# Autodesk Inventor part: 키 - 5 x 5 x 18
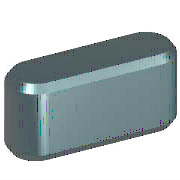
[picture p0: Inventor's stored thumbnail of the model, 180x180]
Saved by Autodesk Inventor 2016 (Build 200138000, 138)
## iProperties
Created: 2012-02
Part Number: 키 - 5 x 5 x 18
Material: 강철, 연강
Description: 키 및 해당 키홈
Document SubType Name: Modeling
Standard: KS B 1311
Designer: mduedu
Standards Organization: KS
Language: ko-KR
Size Designation: 5 x 5 x 18
Categories: <MemberInstance><Categories><Category DisplayName="샤프트 부품" InternalName="7f7aeb1f-a693-4053-b835-cee3144e0d98" Mnemonic="SHFT"><Category DisplayName="키" Interna
Density: 7.86 g/cm^3
Mass: 3.27476 g
Surface Area: 3.57848 cm^2
Volume: 0.416636 cm^3
Appearance: 노란색
IsCustomPart: 1
Author: mduedu
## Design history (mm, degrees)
workplane "Work Plane1"
workplane "Work Plane2"
sketch "스케치1"
  geometry: L1 (2.5, 2.5)-(15.5, 2.5); L2 (15.5, -2.5)-(2.5, -2.5); L3 (0, 9.4)-(0, -7.4) reference; L4 (-5, 0)-(30, 0) reference; L5 (18, 0)-(18, 7); A1 r 2.5 centre (2.5, 0) between (2.5, 2.5) and (2.5, -2.5); A2 r 2.5 centre (15.5, 0) between (15.5, -2.5) and (15.5, 2.5)
  constraints: 6 end point, 5 point on circle, 4 tangent, 3 point on line, 2 centre point, 1 horizontal, 1 parallel, 1 perpendicular
  dimensions: "d0" = 2.5 radius of A1 (= 0.5 x PB); "d13" = 2.5 radius of A2 (= 0.5 x PB); "d14" = 18 distance between parallel lines of L5 L3 (= NLG)
extrude "본체1" new body sketch "스케치1" taper "d3" = 0 deg; stored distance "d4" = 10
workplane "Work Plane3"
body "Solid1"
chamfer "모따기1" distance "d8" = 0.4 (= PHH); stored, may be unused: second distance "d9" = 0.4 (= PHH), angle "d15" = 45 deg
other parameters: "d1" = -3 (= -PNT), "d2" = 2 (= PH - PNT), "NLG" = 18 [user parameter; used in 3 equation terms], "PB" = 5 [user parameter; used in 2 equation terms], "PNT" = 3 [user parameter; used in 2 equation terms], "PH" = 5 [user parameter; used in 1 equation term], "PHH" = 0.4 [user parameter; used in 2 equation terms], "d10" = 0, "d16" = 0, "d17" = 0, "d18" = 0, "WDMIN" = 12 [user parameter], "PLB2" = 18 (= NLG) [user parameter], "WDMAX" = 17 [user parameter], "PLB1" = 18 (= NLG) [user parameter], "RR" = 0.16 [user parameter], "PUEB" = 2.3 [user parameter]
